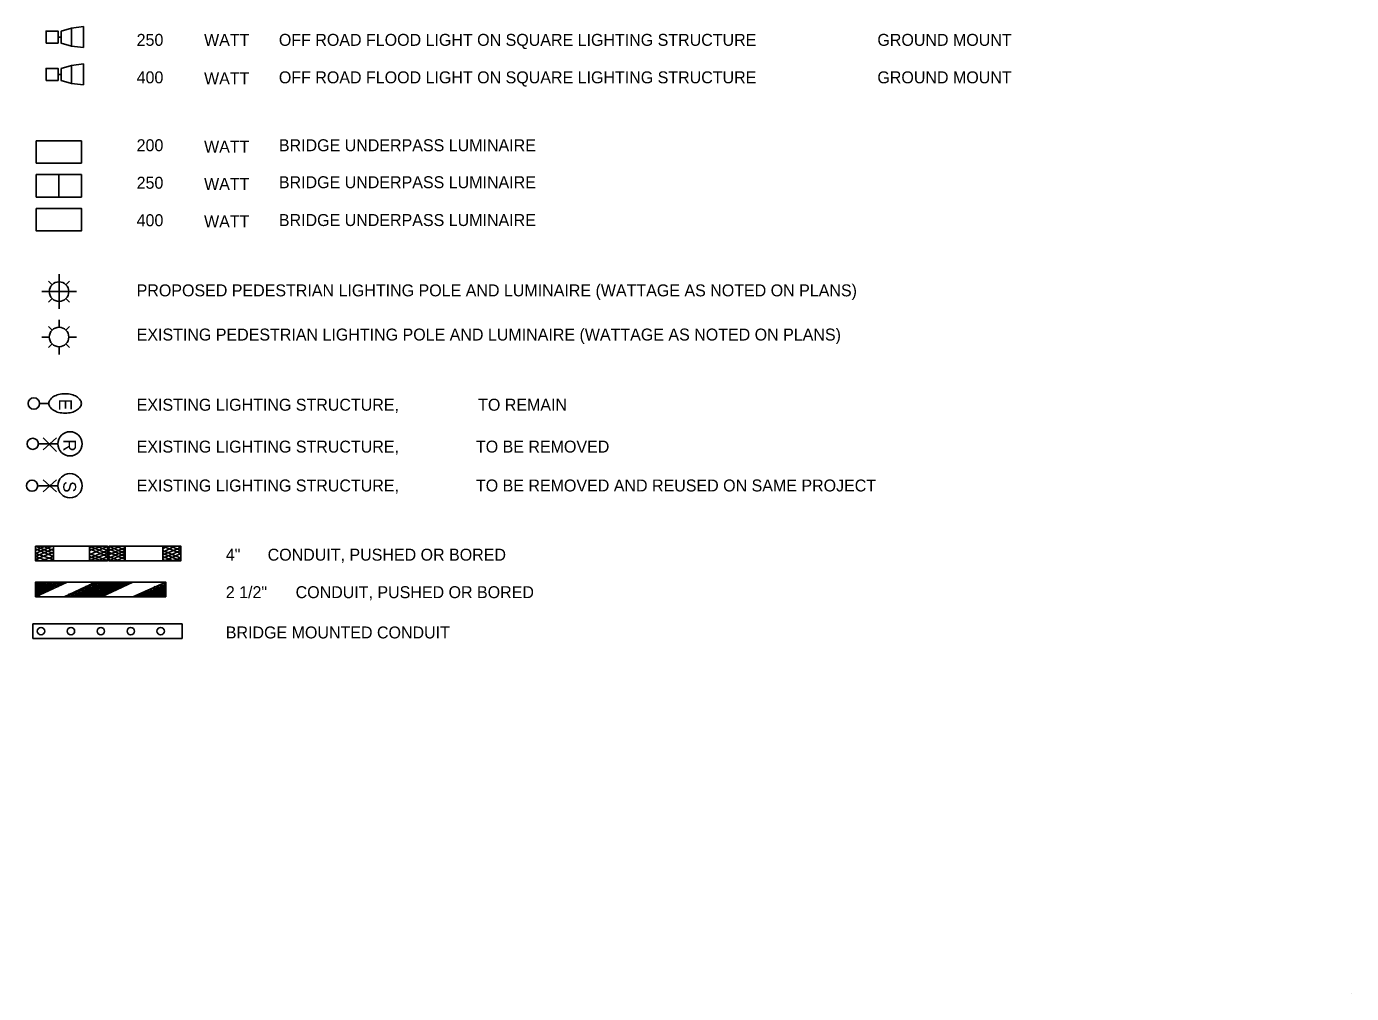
# Model space of a CAD drawing. Extents: x 10019.5 to 10026.1, y 9984.8 to 9994.8.
# Drawn here: x 10019.51 to 10026.15, y 9984.78 to 9989.63 of the extents above; entities that cross this region are included whole.
import ezdxf

# ---------------------------------------------------------------- set-up
doc = ezdxf.new("R2010")
doc.units = 0
for name, color, linetype in [('DETL-LINE', 7, 'Continuous'), ('DETL-NOTE', 7, 'Continuous'), ('TTLB-TEXT', 7, 'Continuous')]:
    doc.layers.add(name, color=color, linetype=linetype)

msp = doc.modelspace()

# ---------------------------------------------------------------- linework, layer by layer
at = {"layer": 'DETL-LINE'}
for p, q in [((10019.665, 9989.5777), (10019.68, 9989.5777)), ((10019.792, 9989.6307), (10019.732, 9989.6227)), ((10019.732, 9989.6227), (10019.732, 9989.5327)), ((10019.792, 9989.5247), (10019.792, 9989.6307)), ((10019.732, 9989.5327), (10019.792, 9989.5247)), ((10019.792, 9989.4427), (10019.732, 9989.4347)), ((10019.792, 9989.3377), (10019.792, 9989.4427)), ((10019.665, 9989.3907), (10019.68, 9989.3907)), ((10019.732, 9989.4347), (10019.732, 9989.3447)), ((10019.732, 9989.3447), (10019.792, 9989.3377)), ((10019.5558, 9989.0577), (10019.6688, 9989.0577)), ((10019.5558, 9988.9447), (10019.5558, 9989.0577)), ((10019.6688, 9989.0577), (10019.7818, 9989.0577)), ((10019.7818, 9989.0577), (10019.7818, 9988.9447)), ((10019.6688, 9988.9447), (10019.5558, 9988.9447)), ((10019.7818, 9988.9447), (10019.6688, 9988.9447)), ((10019.6688, 9988.8882), (10019.5558, 9988.8882)), ((10019.6688, 9988.8882), (10019.7818, 9988.8882)), ((10019.7818, 9988.8882), (10019.7818, 9988.7752)), ((10019.7818, 9988.7752), (10019.6688, 9988.7752)), ((10019.67, 9988.3012), (10019.67, 9988.3882)), ((10019.6355, 9988.3357), (10019.6172, 9988.354)), ((10019.7045, 9988.3357), (10019.7229, 9988.354)), ((10019.583, 9988.3012), (10019.67, 9988.3012)), ((10019.6172, 9988.2483), (10019.6355, 9988.2667)), ((10019.67, 9988.3012), (10019.757, 9988.3012)), ((10019.67, 9988.2142), (10019.67, 9988.3012)), ((10019.7229, 9988.2483), (10019.7045, 9988.2667)), ((10019.6355, 9988.108), (10019.6172, 9988.1264)), ((10019.67, 9988.1222), (10019.67, 9988.1605)), ((10019.7045, 9988.108), (10019.7229, 9988.1264)), ((10019.583, 9988.0735), (10019.6213, 9988.0735)), ((10019.7188, 9988.0735), (10019.757, 9988.0735)), ((10019.6172, 9988.0206), (10019.6355, 9988.039)), ((10019.67, 9987.9865), (10019.67, 9988.0247)), ((10019.7229, 9988.0206), (10019.7045, 9988.039)), ((10019.575, 9987.74), (10019.62, 9987.74)), ((10019.665, 9987.538), (10019.567, 9987.538)), ((10019.657, 9987.5), (10019.59, 9987.568)), ((10019.59, 9987.508), (10019.657, 9987.568)), ((10019.665, 9987.328), (10019.567, 9987.328)), ((10019.657, 9987.298), (10019.59, 9987.358)), ((10019.59, 9987.298), (10019.657, 9987.358)), ((10019.642, 9987.025), (10019.552, 9987.025)), ((10019.552, 9987.025), (10019.552, 9986.951)), ((10019.552, 9987.025), (10019.552, 9987.025)), ((10019.552, 9987.025), (10019.56, 9987.025)), ((10019.552, 9987.003), (10019.598, 9987.025)), ((10019.552, 9986.988), (10019.635, 9987.025)), ((10019.552, 9987.025), (10019.642, 9986.988)), ((10019.552, 9986.973), (10019.642, 9987.011)), ((10019.552, 9987.011), (10019.642, 9986.973)), ((10019.552, 9986.958), (10019.642, 9986.995)), ((10019.552, 9986.988), (10019.642, 9986.958)), ((10019.59, 9987.025), (10019.642, 9987.003)), ((10019.635, 9987.025), (10019.642, 9987.025)), ((10019.642, 9986.951), (10019.642, 9987.025)), ((10019.822, 9986.951), (10019.822, 9987.025)), ((10019.822, 9987.025), (10019.912, 9987.025)), ((10019.822, 9987.018), (10019.845, 9987.025)), ((10019.822, 9987.003), (10019.882, 9987.025)), ((10019.822, 9986.981), (10019.912, 9987.025)), ((10019.822, 9987.025), (10019.912, 9986.988)), ((10019.822, 9987.011), (10019.912, 9986.973)), ((10019.822, 9986.965), (10019.912, 9987.003)), ((10019.822, 9986.951), (10019.912, 9986.988)), ((10019.822, 9986.988), (10019.912, 9986.951)), ((10019.86, 9987.025), (10019.912, 9987.003)), ((10019.898, 9987.025), (10019.912, 9987.018)), ((10019.912, 9987.025), (10019.912, 9986.951)), ((10020.002, 9987.025), (10019.92, 9987.025)), ((10019.92, 9987.025), (10019.92, 9986.951)), ((10019.92, 9987.025), (10019.92, 9987.025)), ((10019.92, 9987.018), (10019.935, 9987.025)), ((10019.92, 9987.003), (10019.98, 9987.025)), ((10019.92, 9987.025), (10020.002, 9986.988)), ((10019.92, 9986.981), (10020.002, 9987.018)), ((10019.92, 9987.011), (10020.002, 9986.973)), ((10019.92, 9986.965), (10020.002, 9987.003)), ((10019.92, 9986.995), (10020.002, 9986.958)), ((10019.92, 9986.951), (10020.002, 9986.988)), ((10019.958, 9987.025), (10020.002, 9987.003)), ((10019.995, 9987.025), (10020.002, 9987.025)), ((10020.002, 9986.951), (10020.002, 9987.025)), ((10020.19, 9987.025), (10020.19, 9986.951)), ((10020.272, 9987.025), (10020.19, 9987.025)), ((10020.19, 9987.011), (10020.212, 9987.025)), ((10020.19, 9986.995), (10020.25, 9987.025)), ((10020.19, 9987.025), (10020.28, 9986.988)), ((10020.19, 9986.981), (10020.28, 9987.018)), ((10020.19, 9986.965), (10020.28, 9987.003)), ((10020.19, 9987.003), (10020.28, 9986.965)), ((10020.19, 9986.988), (10020.28, 9986.951)), ((10020.198, 9986.951), (10020.28, 9986.988)), ((10020.228, 9987.025), (10020.28, 9987.003)), ((10020.265, 9987.025), (10020.28, 9987.018)), ((10020.28, 9986.951), (10020.28, 9987.025)), ((10019.552, 9986.973), (10019.612, 9986.951)), ((10019.552, 9986.958), (10019.575, 9986.951)), ((10019.552, 9986.951), (10019.642, 9986.951)), ((10019.582, 9986.951), (10019.642, 9986.973)), ((10019.62, 9986.951), (10019.642, 9986.958)), ((10019.822, 9986.973), (10019.882, 9986.951)), ((10019.822, 9986.958), (10019.838, 9986.951)), ((10019.912, 9986.951), (10019.822, 9986.951)), ((10019.868, 9986.951), (10019.912, 9986.973)), ((10019.905, 9986.951), (10019.912, 9986.958)), ((10019.92, 9986.973), (10019.972, 9986.951)), ((10019.92, 9986.958), (10019.935, 9986.951)), ((10019.92, 9986.951), (10020.002, 9986.951)), ((10019.958, 9986.951), (10020.002, 9986.973)), ((10020.002, 9986.951), (10020.002, 9986.951)), ((10020.19, 9986.973), (10020.242, 9986.951)), ((10020.19, 9986.958), (10020.205, 9986.951)), ((10020.19, 9986.951), (10020.272, 9986.951)), ((10020.235, 9986.951), (10020.28, 9986.965)), ((10020.28, 9986.951), (10020.28, 9986.951)), ((10019.552, 9986.771), (10019.71, 9986.845)), ((10019.71, 9986.845), (10019.552, 9986.845)), ((10019.552, 9986.845), (10019.552, 9986.771)), ((10019.552, 9986.845), (10019.56, 9986.845)), ((10019.552, 9986.838), (10019.575, 9986.845)), ((10019.552, 9986.823), (10019.598, 9986.845)), ((10019.552, 9986.815), (10019.612, 9986.845)), ((10019.552, 9986.808), (10019.635, 9986.845)), ((10019.552, 9986.801), (10019.658, 9986.845)), ((10019.552, 9986.793), (10019.672, 9986.845)), ((10019.552, 9986.785), (10019.695, 9986.845)), ((10019.552, 9986.838), (10019.628, 9986.808)), ((10019.552, 9986.831), (10019.62, 9986.801)), ((10019.552, 9986.778), (10019.665, 9986.823)), ((10019.552, 9986.823), (10019.612, 9986.801)), ((10019.552, 9986.815), (10019.598, 9986.793)), ((10019.552, 9986.808), (10019.59, 9986.793)), ((10019.552, 9986.801), (10019.582, 9986.785)), ((10019.552, 9986.793), (10019.575, 9986.778)), ((10019.552, 9986.785), (10019.56, 9986.778)), ((10019.56, 9986.845), (10019.635, 9986.808)), ((10019.575, 9986.845), (10019.642, 9986.815)), ((10019.598, 9986.845), (10019.658, 9986.823)), ((10019.612, 9986.845), (10019.665, 9986.823)), ((10019.635, 9986.845), (10019.672, 9986.831)), ((10019.658, 9986.845), (10019.68, 9986.831)), ((10019.672, 9986.845), (10019.695, 9986.838)), ((10019.852, 9986.845), (10019.695, 9986.771)), ((10019.695, 9986.845), (10019.702, 9986.845)), ((10019.702, 9986.771), (10019.875, 9986.845)), ((10019.718, 9986.785), (10019.748, 9986.771)), ((10019.725, 9986.771), (10019.898, 9986.845)), ((10019.732, 9986.785), (10019.762, 9986.771)), ((10019.74, 9986.771), (10019.92, 9986.845)), ((10019.74, 9986.793), (10019.785, 9986.771)), ((10019.748, 9986.793), (10019.808, 9986.771)), ((10019.755, 9986.801), (10019.822, 9986.771)), ((10019.762, 9986.771), (10019.935, 9986.845)), ((10019.762, 9986.801), (10019.845, 9986.771)), ((10019.778, 9986.771), (10019.958, 9986.845)), ((10019.778, 9986.808), (10019.86, 9986.771)), ((10019.785, 9986.815), (10019.882, 9986.771)), ((10019.792, 9986.815), (10019.89, 9986.778)), ((10019.8, 9986.771), (10019.98, 9986.845)), ((10019.8, 9986.823), (10019.905, 9986.778)), ((10019.815, 9986.823), (10019.912, 9986.785)), ((10019.822, 9986.831), (10019.86, 9986.845)), ((10019.822, 9986.771), (10019.995, 9986.845)), ((10019.822, 9986.831), (10019.92, 9986.793)), ((10019.83, 9986.838), (10019.928, 9986.793)), ((10019.838, 9986.771), (10020.018, 9986.845)), ((10019.838, 9986.838), (10019.942, 9986.801)), ((10020.04, 9986.845), (10019.852, 9986.845)), ((10019.852, 9986.845), (10019.95, 9986.801)), ((10019.86, 9986.771), (10020.032, 9986.845)), ((10019.868, 9986.845), (10019.958, 9986.808)), ((10019.882, 9986.771), (10020.04, 9986.845)), ((10019.882, 9986.845), (10019.965, 9986.808)), ((10019.882, 9986.771), (10019.912, 9986.785)), ((10019.905, 9986.845), (10019.972, 9986.815)), ((10019.928, 9986.845), (10019.988, 9986.823)), ((10019.942, 9986.845), (10019.995, 9986.823)), ((10019.965, 9986.845), (10020.002, 9986.831)), ((10019.98, 9986.845), (10020.01, 9986.831)), ((10020.002, 9986.845), (10020.025, 9986.838)), ((10020.025, 9986.845), (10020.032, 9986.838)), ((10020.205, 9986.845), (10020.04, 9986.771)), ((10020.055, 9986.771), (10020.205, 9986.831)), ((10020.07, 9986.771), (10020.205, 9986.823)), ((10020.07, 9986.785), (10020.108, 9986.771)), ((10020.085, 9986.793), (10020.13, 9986.771)), ((10020.092, 9986.771), (10020.205, 9986.815)), ((10020.092, 9986.793), (10020.145, 9986.771)), ((10020.1, 9986.801), (10020.168, 9986.771)), ((10020.108, 9986.771), (10020.205, 9986.808)), ((10020.108, 9986.801), (10020.19, 9986.771)), ((10020.122, 9986.808), (10020.205, 9986.771)), ((10020.13, 9986.808), (10020.205, 9986.778)), ((10020.13, 9986.771), (10020.205, 9986.801)), ((10020.138, 9986.815), (10020.205, 9986.785)), ((10020.145, 9986.823), (10020.205, 9986.801)), ((10020.152, 9986.771), (10020.205, 9986.793)), ((10020.16, 9986.823), (10020.205, 9986.845)), ((10020.16, 9986.823), (10020.205, 9986.808)), ((10020.168, 9986.831), (10020.205, 9986.815)), ((10020.168, 9986.771), (10020.205, 9986.785)), ((10020.175, 9986.831), (10020.205, 9986.823)), ((10020.19, 9986.838), (10020.205, 9986.831)), ((10020.198, 9986.838), (10020.205, 9986.838)), ((10020.205, 9986.771), (10020.205, 9986.845)), ((10019.552, 9986.778), (10019.552, 9986.771)), ((10019.552, 9986.771), (10019.552, 9986.771)), ((10019.695, 9986.771), (10019.882, 9986.771)), ((10019.702, 9986.771), (10019.702, 9986.771)), ((10019.71, 9986.778), (10019.725, 9986.771)), ((10020.04, 9986.771), (10020.205, 9986.771)), ((10020.048, 9986.771), (10020.048, 9986.771)), ((10020.055, 9986.778), (10020.07, 9986.771)), ((10020.062, 9986.778), (10020.085, 9986.771)), ((10020.19, 9986.771), (10020.205, 9986.778)), ((10019.538, 9986.635), (10020.288, 9986.635)), ((10019.538, 9986.635), (10019.538, 9986.561)), ((10020.288, 9986.635), (10020.288, 9986.561)), ((10019.538, 9986.561), (10020.288, 9986.561))]:
    msp.add_line(p, q, dxfattribs=at)
for points in [[(10019.605, 9989.5477), (10019.665, 9989.5477), (10019.665, 9989.6077), (10019.605, 9989.6077)], [(10019.68, 9989.6077), (10019.68, 9989.5477), (10019.732, 9989.5327), (10019.732, 9989.6227)], [(10019.605, 9989.3607), (10019.665, 9989.3607), (10019.665, 9989.4207), (10019.605, 9989.4207)], [(10019.68, 9989.4207), (10019.68, 9989.3607), (10019.732, 9989.3447), (10019.732, 9989.4347)]]:
    msp.add_lwpolyline(points, close=True, dxfattribs=at)
for points in [[(10019.6688, 9988.7752), (10019.6688, 9988.8882), (10019.5558, 9988.8882), (10019.5558, 9988.7752), (10019.6688, 9988.7752)], [(10019.5558, 9988.7187), (10019.5558, 9988.6057), (10019.6688, 9988.6057), (10019.7818, 9988.6057), (10019.7818, 9988.7187), (10019.6688, 9988.7187), (10019.5558, 9988.7187)], [(10019.552, 9987.025), (10019.912, 9987.025), (10019.912, 9986.951), (10019.552, 9986.951), (10019.552, 9987.025)], [(10019.92, 9987.025), (10020.28, 9987.025), (10020.28, 9986.951), (10019.92, 9986.951), (10019.92, 9987.025)], [(10020.205, 9986.771), (10019.552, 9986.771), (10019.552, 9986.845), (10020.205, 9986.845), (10020.205, 9986.771)]]:
    msp.add_lwpolyline(points, dxfattribs=at)
msp.add_circle((10019.67, 9988.0735), 0.0488, dxfattribs=at)
for centre, radius, start, end in [((10019.67, 9988.3012), 0.0488, 0, 180), ((10019.67, 9988.3012), 0.0488, 180, 0), ((10019.6897, 9987.6967), 0.0913, 103.95686, 120.96374), ((10019.7003, 9987.6541), 0.1352, 89.99995, 103.95689), ((10019.7003, 9987.6541), 0.1352, 76.04312, 90.00005), ((10019.7109, 9987.6967), 0.0913, 59.03626, 76.04314), ((10019.5436, 9987.74), 0.0285, 0, 180), ((10019.5436, 9987.74), 0.0285, 180, 0), ((10019.6492, 9987.7404), 0.0303, 145.38045, 180.00004), ((10019.6492, 9987.7404), 0.0303, 179.99997, 214.61956), ((10019.6736, 9987.7236), 0.0599, 120.96377, 145.38051), ((10019.6736, 9987.7573), 0.0599, 214.61949, 239.03623), ((10019.727, 9987.7236), 0.0599, 34.61951, 59.03624), ((10019.727, 9987.7573), 0.0599, 300.96376, 325.38049), ((10019.7514, 9987.7404), 0.0303, 359.99993, 34.61953), ((10019.7514, 9987.7404), 0.0303, 325.38046, 0.00006), ((10019.6897, 9987.7842), 0.0913, 239.03626, 256.04314), ((10019.7003, 9987.8268), 0.1352, 256.0431, 270.00004), ((10019.7003, 9987.8268), 0.1352, 269.99997, 283.9569), ((10019.7109, 9987.7842), 0.0913, 283.95686, 300.96374), ((10019.7247, 9987.5379), 0.0607, 0, 180), ((10019.538, 9987.5379), 0.0281, 0, 180), ((10019.538, 9987.5379), 0.0281, 180, 0), ((10019.7247, 9987.5379), 0.0607, 180, 0), ((10019.7247, 9987.3279), 0.0607, 0, 180), ((10019.5349, 9987.3279), 0.0281, 0, 180), ((10019.5349, 9987.3279), 0.0281, 180, 0), ((10019.7247, 9987.3279), 0.0607, 180, 0), ((10019.5795, 9986.5987), 0.0187, 0, 180), ((10019.5795, 9986.5987), 0.0187, 180, 0), ((10019.7295, 9986.5987), 0.0187, 0, 180), ((10019.7295, 9986.5987), 0.0187, 180, 0), ((10019.8795, 9986.5987), 0.0187, 0, 180), ((10019.8795, 9986.5987), 0.0187, 180, 0), ((10020.0295, 9986.5987), 0.0187, 0, 180), ((10020.0295, 9986.5987), 0.0187, 180, 0), ((10020.1795, 9986.5987), 0.0187, 0, 180), ((10020.1795, 9986.5987), 0.0187, 180, 0)]:
    msp.add_arc(centre, radius, start, end, dxfattribs=at)
at = {"layer": 'TTLB-TEXT'}
msp.add_line((10026.1495, 9984.7815), (10026.1495, 9984.7815), dxfattribs=at)

# ---------------------------------------------------------------- texts
at = {"layer": 'DETL-LINE'}
for s, height, p in [('E', 0.0651, (10019.669, 9987.764)), ('R', 0.0642, (10019.691, 9987.561)), ('S', 0.0642, (10019.691, 9987.351))]:
    msp.add_text(s, height=height, rotation=270, dxfattribs=at).set_placement(p)
at = {"layer": 'DETL-NOTE'}
for s, p in [('250', (10020.059, 9989.5337)), ('WATT', (10020.397, 9989.5337)), ('OFF ROAD FLOOD LIGHT ON SQUARE LIGHTING STRUCTURE', (10020.772, 9989.5337)), ('GROUND MOUNT', (10023.7726, 9989.5337)), ('400', (10020.059, 9989.3457)), ('WATT', (10020.397, 9989.3407)), ('OFF ROAD FLOOD LIGHT ON SQUARE LIGHTING STRUCTURE', (10020.772, 9989.3457)), ('GROUND MOUNT', (10023.7726, 9989.3457)), ('200', (10020.059, 9989.0052)), ('WATT', (10020.397, 9988.9982)), ('BRIDGE UNDERPASS LUMINAIRE', (10020.772, 9989.0052)), ('250', (10020.059, 9988.8172)), ('WATT', (10020.397, 9988.8112)), ('BRIDGE UNDERPASS LUMINAIRE', (10020.772, 9988.8198)), ('400', (10020.059, 9988.6292)), ('WATT', (10020.397, 9988.6232)), ('BRIDGE UNDERPASS LUMINAIRE', (10020.772, 9988.6301)), ('PROPOSED PEDESTRIAN LIGHTING POLE AND LUMINAIRE (WATTAGE AS NOTED ON PLANS)', (10020.059, 9988.2774)), ('EXISTING PEDESTRIAN LIGHTING POLE AND LUMINAIRE (WATTAGE AS NOTED ON PLANS)', (10020.059, 9988.0559)), ('EXISTING LIGHTING STRUCTURE,', (10020.059, 9987.704)), ('TO REMAIN', (10021.771, 9987.704)), ('EXISTING LIGHTING STRUCTURE,', (10020.059, 9987.494)), ('TO BE REMOVED', (10021.76, 9987.494)), ('EXISTING LIGHTING STRUCTURE,', (10020.059, 9987.299)), ('TO BE REMOVED AND REUSED ON SAME PROJECT', (10021.76, 9987.299)), ('4"', (10020.506, 9986.952)), ('CONDUIT, PUSHED OR BORED', (10020.7158, 9986.952)), ('2 1/2"', (10020.506, 9986.764)), ('CONDUIT, PUSHED OR BORED', (10020.856, 9986.764)), ('BRIDGE MOUNTED CONDUIT', (10020.506, 9986.562))]:
    msp.add_text(s, height=0.06, dxfattribs=at).set_placement(p)

doc.saveas('drawing.dxf')
